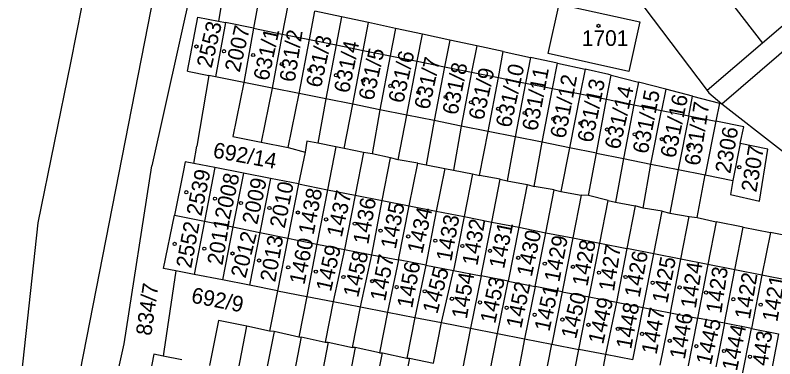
# Model space of a CAD drawing. Extents: x -735249 to -729401, y -1124843 to -1121828.
# Drawn here: x -734473.2 to -734390.6, y -1123645.2 to -1123607.9 of the extents above; entities that cross this region are included whole.
import ezdxf

# ---------------------------------------------------------------- set-up
doc = ezdxf.new("R2010")
doc.units = 0
for name, color, linetype in [('Vrstva 1', 7, 'Continuous'), ('Vrstva 18', 7, 'Continuous'), ('Vrstva 19', 7, 'Continuous'), ('Vrstva 25', 7, 'Continuous'), ('Vrstva 4', 7, 'Continuous')]:
    doc.layers.add(name, color=color, linetype=linetype)

msp = doc.modelspace()

# ---------------------------------------------------------------- linework, layer by layer
at = {"layer": 'Vrstva 1'}
for points in [[(-734466.48, -1123648.3), (-734451.09, -1123569.74)], [(-734462.29, -1123588.13), (-734467.21, -1123613.09)], [(-734405.64, -1123593.23), (-734391.93, -1123610.94)], [(-734411.71, -1123597.86), (-734397.92, -1123616.09)], [(-734453.98, -1123604.55), (-734458.36, -1123624.28)], [(-734450.72, -1123606.17), (-734451.13, -1123608.55)], [(-734446.72, -1123606.14), (-734447.3, -1123609.32)], [(-734385.93, -1123605.8), (-734391.93, -1123610.94)], [(-734443.57, -1123606.82), (-734444.17, -1123609.95)], [(-734415.24, -1123612.06), (-734414.05, -1123606.69)], [(-734414.05, -1123606.69), (-734405.27, -1123608.63)], [(-734441.22, -1123610.54), (-734440.63, -1123607.45)], [(-734437.73, -1123608.07), (-734440.63, -1123607.45)], [(-734454.5, -1123613.98), (-734453.37, -1123608.1)], [(-734453.37, -1123608.1), (-734451.13, -1123608.55)], [(-734450.37, -1123608.7), (-734451.44, -1123614.59)], [(-734451.13, -1123608.55), (-734450.37, -1123608.7)], [(-734447.3, -1123609.32), (-734450.37, -1123608.7)], [(-734437.73, -1123608.07), (-734438.32, -1123611.12)], [(-734434.8, -1123608.7), (-734437.73, -1123608.07)], [(-734435.38, -1123611.72), (-734434.8, -1123608.7)], [(-734431.85, -1123609.34), (-734434.8, -1123608.7)], [(-734405.27, -1123608.63), (-734406.45, -1123614.01)], [(-734447.3, -1123609.32), (-734448.37, -1123615.21)], [(-734431.85, -1123609.34), (-734432.43, -1123612.31)], [(-734428.92, -1123609.97), (-734431.85, -1123609.34)], [(-734444.17, -1123609.95), (-734445.29, -1123615.82)], [(-734429.49, -1123612.9), (-734428.92, -1123609.97)], [(-734425.95, -1123610.61), (-734428.92, -1123609.97)], [(-734396.34, -1123617.53), (-734388.08, -1123610.43)], [(-734442.35, -1123616.41), (-734441.22, -1123610.54)], [(-734438.32, -1123611.12), (-734439.45, -1123616.99)], [(-734425.95, -1123610.61), (-734426.51, -1123613.5)], [(-734423.02, -1123611.24), (-734425.95, -1123610.61)], [(-734423.02, -1123611.24), (-734423.57, -1123614.09)], [(-734420.13, -1123611.86), (-734423.02, -1123611.24)], [(-734391.93, -1123610.94), (-734397.92, -1123616.09)], [(-734436.51, -1123617.58), (-734435.38, -1123611.72)], [(-734420.66, -1123614.67), (-734420.13, -1123611.86)], [(-734420.13, -1123611.86), (-734417.18, -1123612.5)], [(-734406.45, -1123614.01), (-734415.24, -1123612.06)], [(-734432.43, -1123612.31), (-734433.57, -1123618.17)], [(-734430.62, -1123618.76), (-734429.49, -1123612.9)], [(-734417.18, -1123612.5), (-734417.71, -1123615.27)], [(-734414.24, -1123613.13), (-734417.18, -1123612.5)], [(-734467.21, -1123613.09), (-734470.76, -1123630.45)], [(-734426.51, -1123613.5), (-734427.64, -1123619.35)], [(-734414.77, -1123615.86), (-734414.24, -1123613.13)], [(-734414.24, -1123613.13), (-734411.22, -1123613.78)], [(-734454.5, -1123613.98), (-734452.15, -1123614.45)], [(-734452.15, -1123614.45), (-734453.48, -1123622.14)], [(-734451.44, -1123614.59), (-734452.15, -1123614.45)], [(-734448.37, -1123615.21), (-734451.44, -1123614.59)], [(-734423.57, -1123614.09), (-734424.69, -1123619.94)], [(-734411.22, -1123613.78), (-734411.76, -1123616.46)], [(-734408.62, -1123614.34), (-734411.22, -1123613.78)], [(-734408.88, -1123617.04), (-734408.38, -1123614.4)], [(-734408.38, -1123614.4), (-734408.62, -1123614.34)], [(-734408.38, -1123614.4), (-734405.41, -1123615.17)], [(-734448.37, -1123615.21), (-734449.55, -1123621.09)], [(-734421.77, -1123620.53), (-734420.66, -1123614.67)], [(-734417.71, -1123615.27), (-734418.83, -1123621.12)], [(-734405.41, -1123615.17), (-734405.9, -1123617.64)], [(-734402.45, -1123615.94), (-734405.41, -1123615.17)], [(-734445.29, -1123615.82), (-734446.47, -1123621.71)], [(-734415.9, -1123621.7), (-734414.77, -1123615.86)], [(-734402.45, -1123615.94), (-734402.9, -1123618.24)], [(-734399.53, -1123616.7), (-734402.45, -1123615.94)], [(-734397.92, -1123616.09), (-734397.74, -1123616.33)], [(-734443.53, -1123622.29), (-734442.35, -1123616.41)], [(-734439.45, -1123616.99), (-734440.3, -1123621.8)], [(-734411.76, -1123616.46), (-734412.93, -1123622.3)], [(-734409.99, -1123622.89), (-734408.88, -1123617.04)], [(-734399.95, -1123618.84), (-734399.53, -1123616.7)], [(-734399.53, -1123616.7), (-734396.6, -1123617.46)], [(-734397.74, -1123616.33), (-734396.34, -1123617.53)], [(-734437.45, -1123622.4), (-734436.51, -1123617.58)], [(-734405.9, -1123617.64), (-734407.06, -1123623.47)], [(-734396.6, -1123617.46), (-734397, -1123619.43)], [(-734396.6, -1123617.46), (-734396.34, -1123617.53)], [(-734396.34, -1123617.53), (-734384.23, -1123626.94)], [(-734433.57, -1123618.17), (-734434.4, -1123622.95)], [(-734404.05, -1123624.07), (-734402.9, -1123618.24)], [(-734431.55, -1123623.6), (-734430.62, -1123618.76)], [(-734427.64, -1123619.35), (-734428.5, -1123624.15)], [(-734399.95, -1123618.84), (-734401.09, -1123624.67)], [(-734397, -1123619.43), (-734398.17, -1123625.25)], [(-734393.96, -1123620.04), (-734397, -1123619.43)], [(-734424.69, -1123619.94), (-734425.55, -1123624.75)], [(-734394.33, -1123621.84), (-734393.96, -1123620.04)], [(-734449.55, -1123621.09), (-734446.47, -1123621.71)], [(-734422.7, -1123625.3), (-734421.77, -1123620.53)], [(-734418.83, -1123621.12), (-734419.7, -1123625.9)], [(-734446.47, -1123621.71), (-734443.53, -1123622.29)], [(-734441.51, -1123621.6), (-734441.7, -1123622.8)], [(-734440.3, -1123621.8), (-734441.51, -1123621.6)], [(-734438.35, -1123622.22), (-734440.3, -1123621.8)], [(-734416.75, -1123626.5), (-734415.9, -1123621.7)], [(-734394.33, -1123621.84), (-734395.13, -1123625.86)], [(-734391.34, -1123622.44), (-734394.33, -1123621.84)], [(-734453.81, -1123624.01), (-734453.48, -1123622.14)], [(-734443.53, -1123622.29), (-734441.7, -1123622.8)], [(-734441.7, -1123622.8), (-734442.42, -1123626.24)], [(-734438.35, -1123622.22), (-734439.26, -1123626.86)], [(-734437.45, -1123622.4), (-734438.35, -1123622.22)], [(-734435.33, -1123622.81), (-734437.45, -1123622.4)], [(-734435.33, -1123622.81), (-734436.24, -1123627.45)], [(-734434.4, -1123622.95), (-734435.33, -1123622.81)], [(-734412.93, -1123622.3), (-734413.85, -1123627.05)], [(-734392.26, -1123628.1), (-734391.34, -1123622.44)], [(-734432.38, -1123623.39), (-734434.4, -1123622.95)], [(-734433.29, -1123628.03), (-734432.38, -1123623.39)], [(-734431.55, -1123623.6), (-734432.38, -1123623.39)], [(-734429.44, -1123623.97), (-734431.55, -1123623.6)], [(-734410.85, -1123627.5), (-734409.99, -1123622.89)], [(-734407.06, -1123623.47), (-734407.9, -1123628.2)], [(-734461.39, -1123643.59), (-734458.36, -1123624.28)], [(-734454.73, -1123623.83), (-734454.96, -1123624.94)], [(-734453.81, -1123624.01), (-734454.73, -1123623.83)], [(-734451.5, -1123624.46), (-734453.81, -1123624.01)], [(-734451.5, -1123624.46), (-734452.63, -1123630.27)], [(-734448.41, -1123625.07), (-734451.5, -1123624.46)], [(-734430.35, -1123628.61), (-734429.44, -1123623.97)], [(-734429.44, -1123623.97), (-734428.5, -1123624.15)], [(-734428.5, -1123624.15), (-734426.5, -1123624.55)], [(-734404.9, -1123628.85), (-734404.05, -1123624.07)], [(-734454.96, -1123624.94), (-734455.91, -1123629.62)], [(-734448.41, -1123625.07), (-734449.56, -1123630.9)], [(-734445.46, -1123625.64), (-734448.41, -1123625.07)], [(-734426.5, -1123624.55), (-734427.41, -1123629.18)], [(-734426.5, -1123624.55), (-734425.55, -1123624.75)], [(-734425.55, -1123624.75), (-734423.47, -1123625.14)], [(-734423.47, -1123625.14), (-734424.37, -1123629.78)], [(-734423.47, -1123625.14), (-734422.7, -1123625.3)], [(-734420.47, -1123625.73), (-734422.7, -1123625.3)], [(-734401.09, -1123624.67), (-734402, -1123629.4)], [(-734399.01, -1123629.89), (-734398.17, -1123625.25)], [(-734398.17, -1123625.25), (-734395.13, -1123625.86)], [(-734445.46, -1123625.64), (-734446.62, -1123631.51)], [(-734442.42, -1123626.24), (-734445.46, -1123625.64)], [(-734421.38, -1123630.37), (-734420.47, -1123625.73)], [(-734420.47, -1123625.73), (-734419.7, -1123625.9)], [(-734419.7, -1123625.9), (-734417.53, -1123626.31)], [(-734395.13, -1123625.86), (-734395.39, -1123627.38)], [(-734442.42, -1123626.24), (-734443.58, -1123632.14)], [(-734439.26, -1123626.86), (-734440.42, -1123632.76)], [(-734417.53, -1123626.31), (-734418.44, -1123630.94)], [(-734417.53, -1123626.31), (-734416.75, -1123626.5)], [(-734414.58, -1123626.88), (-734416.75, -1123626.5)], [(-734415.49, -1123631.53), (-734414.58, -1123626.88)], [(-734414.58, -1123626.88), (-734413.85, -1123627.05)], [(-734436.24, -1123627.45), (-734437.4, -1123633.34)], [(-734413.85, -1123627.05), (-734411.64, -1123627.46)], [(-734411.64, -1123627.46), (-734412.56, -1123632.1)], [(-734410.85, -1123627.5), (-734411.64, -1123627.46)], [(-734408.71, -1123628.04), (-734410.85, -1123627.5)], [(-734395.39, -1123627.38), (-734392.26, -1123628.1)], [(-734434.44, -1123633.92), (-734433.29, -1123628.03)], [(-734431.51, -1123634.48), (-734430.35, -1123628.61)], [(-734409.62, -1123632.68), (-734408.71, -1123628.04)], [(-734408.71, -1123628.04), (-734407.9, -1123628.2)], [(-734407.9, -1123628.2), (-734405.76, -1123628.62)], [(-734405.76, -1123628.62), (-734406.67, -1123633.26)], [(-734404.9, -1123628.85), (-734405.76, -1123628.62)], [(-734427.41, -1123629.18), (-734428.56, -1123635.06)], [(-734402.83, -1123629.19), (-734404.9, -1123628.85)], [(-734403.74, -1123633.83), (-734402.83, -1123629.19)], [(-734402.83, -1123629.19), (-734402, -1123629.4)], [(-734402, -1123629.4), (-734399.88, -1123629.77)], [(-734457.09, -1123635.42), (-734455.91, -1123629.62)], [(-734455.91, -1123629.62), (-734452.63, -1123630.27)], [(-734452.63, -1123630.27), (-734453.77, -1123636.07)], [(-734452.63, -1123630.27), (-734449.56, -1123630.9)], [(-734424.37, -1123629.78), (-734425.53, -1123635.65)], [(-734400.8, -1123634.41), (-734399.88, -1123629.77)], [(-734399.88, -1123629.77), (-734399.01, -1123629.89)], [(-734399.01, -1123629.89), (-734396.94, -1123630.35)], [(-734470.76, -1123630.45), (-734473.24, -1123653.15)], [(-734449.56, -1123630.9), (-734450.69, -1123636.66)], [(-734449.56, -1123630.9), (-734446.62, -1123631.51)], [(-734422.53, -1123636.23), (-734421.38, -1123630.37)], [(-734418.44, -1123630.94), (-734419.59, -1123636.8)], [(-734396.94, -1123630.35), (-734397.85, -1123634.99)], [(-734394.01, -1123630.92), (-734396.94, -1123630.35)], [(-734394.93, -1123635.56), (-734394.01, -1123630.92)], [(-734394.01, -1123630.92), (-734391.06, -1123631.5)], [(-734446.62, -1123631.51), (-734447.75, -1123637.24)], [(-734446.62, -1123631.51), (-734443.58, -1123632.14)], [(-734416.64, -1123637.37), (-734415.49, -1123631.53)], [(-734391.06, -1123631.5), (-734391.98, -1123636.14)], [(-734388.13, -1123632.08), (-734391.06, -1123631.5)], [(-734443.58, -1123632.14), (-734444.7, -1123637.83)], [(-734443.58, -1123632.14), (-734440.42, -1123632.76)], [(-734440.42, -1123632.76), (-734441.51, -1123638.45)], [(-734440.42, -1123632.76), (-734437.4, -1123633.34)], [(-734412.56, -1123632.1), (-734413.7, -1123637.94)], [(-734410.77, -1123638.51), (-734409.62, -1123632.68)], [(-734437.4, -1123633.34), (-734438.64, -1123639.01)], [(-734437.4, -1123633.34), (-734434.44, -1123633.92)], [(-734406.67, -1123633.26), (-734407.82, -1123639.08)], [(-734435.67, -1123639.58), (-734434.44, -1123633.92)], [(-734434.44, -1123633.92), (-734431.51, -1123634.48)], [(-734404.89, -1123639.65), (-734403.74, -1123633.83)], [(-734401.94, -1123640.22), (-734400.8, -1123634.41)], [(-734431.51, -1123634.48), (-734432.72, -1123640.16)], [(-734428.56, -1123635.06), (-734431.51, -1123634.48)], [(-734428.56, -1123635.06), (-734429.75, -1123640.73)], [(-734428.56, -1123635.06), (-734425.53, -1123635.65)], [(-734397.85, -1123634.99), (-734398.99, -1123640.8)], [(-734455.76, -1123635.68), (-734457.09, -1123635.42)], [(-734455.76, -1123635.68), (-734457.05, -1123644.44)], [(-734453.77, -1123636.07), (-734455.76, -1123635.68)], [(-734450.69, -1123636.66), (-734453.77, -1123636.07)], [(-734426.86, -1123641.3), (-734425.53, -1123635.65)], [(-734425.53, -1123635.65), (-734422.53, -1123636.23)], [(-734396.06, -1123641.36), (-734394.93, -1123635.56)], [(-734447.75, -1123637.24), (-734450.69, -1123636.66)], [(-734422.53, -1123636.23), (-734423.7, -1123641.91)], [(-734419.59, -1123636.8), (-734422.53, -1123636.23)], [(-734420.75, -1123642.49), (-734419.59, -1123636.8)], [(-734419.59, -1123636.8), (-734416.64, -1123637.37)], [(-734391.98, -1123636.14), (-734393.11, -1123641.94)], [(-734444.7, -1123637.83), (-734447.75, -1123637.24)], [(-734416.64, -1123637.37), (-734417.8, -1123643.06)], [(-734413.7, -1123637.94), (-734416.64, -1123637.37)], [(-734444.7, -1123637.83), (-734445.56, -1123642.24)], [(-734441.51, -1123638.45), (-734442.37, -1123642.87)], [(-734413.7, -1123637.94), (-734414.85, -1123643.64)], [(-734413.7, -1123637.94), (-734410.77, -1123638.51)], [(-734411.9, -1123644.21), (-734410.77, -1123638.51)], [(-734410.77, -1123638.51), (-734407.82, -1123639.08)], [(-734438.64, -1123639.01), (-734439.5, -1123643.43)], [(-734407.82, -1123639.08), (-734408.99, -1123644.78)], [(-734407.82, -1123639.08), (-734404.89, -1123639.65)], [(-734436.53, -1123644.01), (-734435.67, -1123639.58)], [(-734432.72, -1123640.16), (-734433.58, -1123644.58)], [(-734406.04, -1123645.35), (-734404.89, -1123639.65)], [(-734404.89, -1123639.65), (-734401.94, -1123640.22)], [(-734401.94, -1123640.22), (-734403.08, -1123645.93)], [(-734401.94, -1123640.22), (-734398.99, -1123640.8)], [(-734429.75, -1123640.73), (-734430.62, -1123645.16)], [(-734398.99, -1123640.8), (-734400.13, -1123646.5)], [(-734396.06, -1123641.36), (-734398.99, -1123640.8)], [(-734451.11, -1123641.06), (-734452.08, -1123645.96)], [(-734448.02, -1123641.67), (-734451.11, -1123641.06)], [(-734448.99, -1123646.57), (-734448.02, -1123641.67)], [(-734445.56, -1123642.24), (-734448.02, -1123641.67)], [(-734427.72, -1123645.72), (-734426.86, -1123641.3)], [(-734396.06, -1123641.36), (-734397.19, -1123647.07)], [(-734393.11, -1123641.94), (-734396.06, -1123641.36)], [(-734445.06, -1123642.25), (-734446.02, -1123647.16)], [(-734445.06, -1123642.25), (-734445.56, -1123642.24)], [(-734442.37, -1123642.87), (-734445.06, -1123642.25)], [(-734423.7, -1123641.91), (-734424.56, -1123646.34)], [(-734421.61, -1123646.91), (-734420.75, -1123642.49)], [(-734394.24, -1123647.65), (-734393.11, -1123641.94)], [(-734393.11, -1123641.94), (-734390.18, -1123642.51)], [(-734390.18, -1123642.51), (-734391.28, -1123648.22)], [(-734442.11, -1123642.84), (-734443.08, -1123647.74)], [(-734442.37, -1123642.87), (-734442.11, -1123642.84)], [(-734442.11, -1123642.84), (-734439.5, -1123643.43)], [(-734439.17, -1123643.42), (-734440.14, -1123648.32)], [(-734439.5, -1123643.43), (-734439.17, -1123643.42)], [(-734439.17, -1123643.42), (-734436.53, -1123644.01)], [(-734417.8, -1123643.06), (-734418.66, -1123647.49)], [(-734464.22, -1123656.34), (-734461.39, -1123643.59)], [(-734436.23, -1123644), (-734437.2, -1123648.9)], [(-734436.23, -1123644), (-734436.53, -1123644.01)], [(-734433.58, -1123644.58), (-734436.23, -1123644)], [(-734415.7, -1123648.06), (-734414.85, -1123643.64)], [(-734412.76, -1123648.63), (-734411.9, -1123644.21)], [(-734458.15, -1123644.74), (-734459.28, -1123650.52)], [(-734457.13, -1123644.95), (-734458.15, -1123644.74)], [(-734457.05, -1123644.44), (-734457.13, -1123644.95)], [(-734455.12, -1123645.36), (-734457.13, -1123644.95)], [(-734434.25, -1123649.48), (-734433.28, -1123644.58)], [(-734433.58, -1123644.58), (-734433.28, -1123644.58)], [(-734433.28, -1123644.58), (-734430.62, -1123645.16)], [(-734430.34, -1123645.16), (-734431.31, -1123650.07)], [(-734430.62, -1123645.16), (-734430.34, -1123645.16)], [(-734430.34, -1123645.16), (-734427.72, -1123645.72)], [(-734408.99, -1123644.78), (-734409.84, -1123649.2)]]:
    msp.add_lwpolyline(points, dxfattribs=at)
at = {"layer": 'Vrstva 25'}
for centre in [(-734409.76, -1123609.06), (-734453.52, -1123611.3), (-734450.52, -1123611.82), (-734447.34, -1123612.23), (-734444.22, -1123613.21), (-734441.21, -1123613.85), (-734438.32, -1123614.42), (-734435.37, -1123615), (-734432.42, -1123615.58), (-734429.36, -1123616.28), (-734426.39, -1123616.79), (-734423.63, -1123617.37), (-734420.68, -1123618.07), (-734417.79, -1123618.53), (-734414.67, -1123619.17), (-734411.72, -1123619.63), (-734408.83, -1123620.32), (-734405.82, -1123620.84), (-734402.87, -1123621.37), (-734399.98, -1123622.12), (-734394.45, -1123624.42), (-734454.62, -1123627.14), (-734451.5, -1123627.84), (-734448.67, -1123628.3), (-734445.57, -1123628.85), (-734442.48, -1123629.34), (-734439.41, -1123630.09), (-734436.29, -1123630.55), (-734433.48, -1123631.31), (-734430.47, -1123631.94), (-734455.89, -1123632.75), (-734427.52, -1123632.4), (-734452.66, -1123633.27), (-734449.59, -1123633.79), (-734424.58, -1123632.98), (-734421.57, -1123633.5), (-734446.7, -1123634.55), (-734418.5, -1123634.26), (-734443.53, -1123635.3), (-734415.61, -1123634.89), (-734412.55, -1123635.24), (-734440.52, -1123635.76), (-734409.71, -1123635.87), (-734437.52, -1123636.34), (-734434.39, -1123636.8), (-734406.82, -1123636.34), (-734403.87, -1123636.97), (-734431.73, -1123637.44), (-734428.67, -1123637.9), (-734400.94, -1123637.48), (-734425.72, -1123638.71), (-734398.05, -1123638.04), (-734422.66, -1123639.11), (-734395.09, -1123638.76), (-734392.11, -1123639.35), (-734419.76, -1123639.69), (-734416.71, -1123640.45), (-734413.69, -1123640.97), (-734410.86, -1123641.54), (-734407.66, -1123641.98), (-734405.02, -1123642.53), (-734402.01, -1123643.28), (-734399.12, -1123643.86), (-734396.11, -1123644.38), (-734393.28, -1123645.01)]:
    msp.add_circle(centre, 0.175, dxfattribs=at)
at = {"layer": 'Vrstva 4'}
for points in [[(-734447.3, -1123609.32), (-734444.17, -1123609.95)], [(-734444.17, -1123609.95), (-734441.22, -1123610.54)], [(-734441.22, -1123610.54), (-734438.32, -1123611.12)], [(-734438.32, -1123611.12), (-734435.38, -1123611.72)], [(-734435.38, -1123611.72), (-734432.43, -1123612.31)], [(-734432.43, -1123612.31), (-734429.49, -1123612.9)], [(-734429.49, -1123612.9), (-734426.51, -1123613.5)], [(-734426.51, -1123613.5), (-734423.57, -1123614.09)], [(-734423.57, -1123614.09), (-734420.66, -1123614.67)], [(-734445.29, -1123615.82), (-734448.37, -1123615.21)], [(-734420.66, -1123614.67), (-734417.71, -1123615.27)], [(-734417.71, -1123615.27), (-734414.77, -1123615.86)], [(-734442.35, -1123616.41), (-734445.29, -1123615.82)], [(-734414.77, -1123615.86), (-734411.76, -1123616.46)], [(-734439.45, -1123616.99), (-734442.35, -1123616.41)], [(-734436.51, -1123617.58), (-734439.45, -1123616.99)], [(-734411.76, -1123616.46), (-734408.88, -1123617.04)], [(-734408.88, -1123617.04), (-734405.9, -1123617.64)], [(-734433.57, -1123618.17), (-734436.51, -1123617.58)], [(-734405.9, -1123617.64), (-734402.9, -1123618.24)], [(-734430.62, -1123618.76), (-734433.57, -1123618.17)], [(-734402.9, -1123618.24), (-734399.95, -1123618.84)], [(-734427.64, -1123619.35), (-734430.62, -1123618.76)], [(-734424.69, -1123619.94), (-734427.64, -1123619.35)], [(-734399.95, -1123618.84), (-734397, -1123619.43)], [(-734421.77, -1123620.53), (-734424.69, -1123619.94)], [(-734418.83, -1123621.12), (-734421.77, -1123620.53)], [(-734415.9, -1123621.7), (-734418.83, -1123621.12)], [(-734412.93, -1123622.3), (-734415.9, -1123621.7)], [(-734409.99, -1123622.89), (-734412.93, -1123622.3)], [(-734409.99, -1123622.89), (-734407.06, -1123623.47)], [(-734407.06, -1123623.47), (-734404.05, -1123624.07)], [(-734404.05, -1123624.07), (-734401.09, -1123624.67)], [(-734401.09, -1123624.67), (-734398.17, -1123625.25)], [(-734442.42, -1123626.24), (-734439.26, -1123626.86)], [(-734439.26, -1123626.86), (-734436.24, -1123627.45)], [(-734436.24, -1123627.45), (-734433.29, -1123628.03)], [(-734433.29, -1123628.03), (-734430.35, -1123628.61)], [(-734430.35, -1123628.61), (-734427.41, -1123629.18)], [(-734427.41, -1123629.18), (-734424.37, -1123629.78)], [(-734424.37, -1123629.78), (-734421.38, -1123630.37)], [(-734421.38, -1123630.37), (-734418.44, -1123630.94)], [(-734418.44, -1123630.94), (-734415.49, -1123631.53)], [(-734415.49, -1123631.53), (-734412.56, -1123632.1)], [(-734412.56, -1123632.1), (-734409.62, -1123632.68)], [(-734409.62, -1123632.68), (-734406.67, -1123633.26)], [(-734403.74, -1123633.83), (-734406.67, -1123633.26)], [(-734400.8, -1123634.41), (-734403.74, -1123633.83)], [(-734397.85, -1123634.99), (-734400.8, -1123634.41)], [(-734394.93, -1123635.56), (-734397.85, -1123634.99)], [(-734391.98, -1123636.14), (-734394.93, -1123635.56)], [(-734389.04, -1123636.72), (-734391.98, -1123636.14)], [(-734444.7, -1123637.83), (-734441.51, -1123638.45)], [(-734441.51, -1123638.45), (-734438.64, -1123639.01)], [(-734438.64, -1123639.01), (-734435.67, -1123639.58)], [(-734435.67, -1123639.58), (-734432.72, -1123640.16)], [(-734432.72, -1123640.16), (-734429.75, -1123640.73)], [(-734429.75, -1123640.73), (-734426.86, -1123641.3)], [(-734426.86, -1123641.3), (-734423.7, -1123641.91)], [(-734423.7, -1123641.91), (-734420.75, -1123642.49)], [(-734420.75, -1123642.49), (-734417.8, -1123643.06)], [(-734417.8, -1123643.06), (-734414.85, -1123643.64)], [(-734414.85, -1123643.64), (-734411.9, -1123644.21)], [(-734408.99, -1123644.78), (-734411.9, -1123644.21)], [(-734406.04, -1123645.35), (-734408.99, -1123644.78)]]:
    msp.add_lwpolyline(points, dxfattribs=at)

# ---------------------------------------------------------------- texts
at = {"layer": 'Vrstva 18'}
for s, rotation, p in [('692/14', 349.60278, (-734451.798, -1123623.35)), ('834/7', 81.90065, (-734458.439, -1123642.784)), ('692/9', 349.00278, (-734454.166, -1123639.112))]:
    msp.add_text(s, height=1.7, rotation=rotation, dxfattribs=at).set_placement(p)
at = {"layer": 'Vrstva 19'}
for s, rotation, p in [('2553', 76.80061, (-734451.879, -1123613.73)), ('2007', 76.90061, (-734448.819, -1123614.18)), ('631/1', 77.60062, (-734445.692, -1123615.112)), ('631/2', 81.10064, (-734442.826, -1123615.242)), ('631/3', 77.60062, (-734439.972, -1123615.862)), ('631/4', 78.50062, (-734436.916, -1123616.445)), ('631/5', 77.80062, (-734434.253, -1123617.253)), ('631/6', 77.50062, (-734431.011, -1123617.542)), ('631/7', 77.90062, (-734428.183, -1123618.233)), ('631/8', 78.70063, (-734425.116, -1123618.815)), ('631/9', 77.60062, (-734422.282, -1123619.392)), ('631/10', 77.50062, (-734419.321, -1123620.202)), ('631/11', 79.30063, (-734416.439, -1123620.557)), ('631/12', 79.20063, (-734413.378, -1123621.367)), ('631/13', 78.50062, (-734410.426, -1123621.825)), ('631/14', 77.10061, (-734407.47, -1123622.571)), ('631/15', 78.90063, (-734404.407, -1123623.036)), ('631/16', 78.40062, (-734401.405, -1123623.504)), ('631/17', 81.10064, (-734398.756, -1123624.322)), ('2306', 79.90064, (-734395.421, -1123625.169)), ('2307', 80.50064, (-734392.584, -1123627.2)), ('2539', 78.30062, (-734452.985, -1123629.794)), ('2008', 77.40062, (-734449.911, -1123630.202)), ('2009', 77.80062, (-734446.913, -1123630.723)), ('2010', 78.50062, (-734443.916, -1123631.125)), ('1438', 79.00063, (-734440.778, -1123631.836)), ('1437', 77.60062, (-734437.712, -1123632.112)), ('1436', 80.10064, (-734434.822, -1123632.869)), ('1435', 78.60062, (-734431.836, -1123633.385)), ('1434', 77.10061, (-734428.95, -1123633.901)), ('2011', 80.70064, (-734450.685, -1123635.131)), ('1433', 79.70063, (-734425.781, -1123634.718)), ('1432', 80.20064, (-734422.943, -1123635.179)), ('2552', 79.40063, (-734454.089, -1123635.467)), ('1431', 78.40062, (-734420.045, -1123635.524)), ('2012', 75.8006, (-734448.174, -1123636.558)), ('2013', 79.60063, (-734444.95, -1123636.968)), ('1430', 77.90062, (-734417.033, -1123636.393)), ('1429', 79.10063, (-734414.028, -1123636.976)), ('1460', 78.40062, (-734441.775, -1123637.254)), ('1428', 79.60063, (-734410.97, -1123637.438)), ('1459', 77.30061, (-734438.881, -1123638.011)), ('1458', 77.00061, (-734435.929, -1123638.651)), ('1427', 81.10064, (-734408.086, -1123637.972)), ('1426', 79.30063, (-734405.299, -1123638.647)), ('1457', 78.70063, (-734432.986, -1123639.055)), ('1425', 79.00063, (-734402.288, -1123639.286)), ('1456', 79.70063, (-734430.041, -1123639.808)), ('1424', 81.40065, (-734399.177, -1123639.833)), ('1455', 75.2006, (-734427.312, -1123640.436)), ('1454', 80.50064, (-734424.094, -1123640.97)), ('1423', 81.50065, (-734396.408, -1123640.363)), ('1422', 80.30064, (-734393.293, -1123641.01)), ('1453', 77.70062, (-734421.012, -1123641.482)), ('1452', 78.30062, (-734418.175, -1123642.004)), ('1421', 79.90064, (-734390.311, -1123641.289)), ('1451', 77.80062, (-734415.113, -1123642.343)), ('1450', 76.60061, (-734412.218, -1123643.16)), ('1449', 77.10061, (-734409.27, -1123643.731)), ('1448', 79.70063, (-734406.211, -1123644.258)), ('1447', 79.20063, (-734403.448, -1123644.837)), ('1446', 79.80063, (-734400.381, -1123645.358)), ('1445', 77.00061, (-734397.539, -1123645.991)), ('1444', 78.10062, (-734394.704, -1123646.634)), ('1443', 82.00065, (-734391.54, -1123647.325))]:
    msp.add_text(s, height=1.7, rotation=rotation, dxfattribs=at).set_placement(p)
msp.add_text('1701', height=1.7, dxfattribs=at).set_placement((-734411.57, -1123611.24))

doc.saveas('drawing.dxf')
